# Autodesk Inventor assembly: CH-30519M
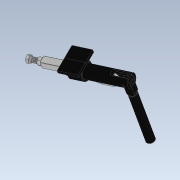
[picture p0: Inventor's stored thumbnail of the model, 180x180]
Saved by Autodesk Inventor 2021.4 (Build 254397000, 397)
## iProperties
Company: Microsoft
Created: 2017-11
Part Number: CH-30519M
Description: STEP AP203
Document SubType Name: Assembly
Designer: user
Stock Number: DOCISK LINIOWY
Sending System: SolidWorks 2015
Preprocessor: SwSTEP 2.0
Title: CH-30519M.STEP
Author: Windows
Revision Number: ÈÎºÎ
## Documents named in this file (14)
- Y:\CAD CLAMPS\Dociski liniowe\CH-30519M\CH-30519M.iam
- Y:\CAD CLAMPS\Dociski liniowe\CH-30519M\CH-30519M-05 CREST STALK.ipt
- Y:\CAD CLAMPS\Dociski liniowe\CH-30519M\CH-30519M-02 LEAD TUBE.ipt
- Y:\CAD CLAMPS\Dociski liniowe\CH-30519M\CH-30519M-04 CONNECTING-PLATE.ipt
- Y:\CAD CLAMPS\Dociski liniowe\CH-30519M\CH-30519M-10.ipt
- Y:\CAD CLAMPS\Dociski liniowe\CH-30519M\CH-30519M-07.ipt
- Y:\CAD CLAMPS\Dociski liniowe\CH-30519M\CH-30519M-06.ipt
- Y:\CAD CLAMPS\Dociski liniowe\CH-30519M\CH-30519M-08.ipt
- Y:\CAD CLAMPS\Dociski liniowe\CH-30519M\CH-30519M-03 HANDLE.ipt
- Y:\CAD CLAMPS\Dociski liniowe\CH-30519M\CH-30519M-11.ipt
- Y:\CAD CLAMPS\Dociski liniowe\CH-30519M\CH-30519M-09.ipt
- Y:\CAD CLAMPS\Dociski liniowe\CH-30519M\M12 Nut.ipt
- Y:\CAD CLAMPS\Dociski liniowe\CH-30519M\M12X50.ipt
- Y:\CAD CLAMPS\Dociski liniowe\CH-30519M\30519-01_Ä¬ÈÏ_°´¼Ó¹¤_.ipt
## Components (14 placed, 14 different names)
1. CH-30519M-05 CREST STALK_1
2. CH-30519M-02 LEAD TUBE_2
3. CH-30519M-04 CONNECTING-PLATE_3
4. CH-30519M-10_4
5. CH-30519M-10_5
6. CH-30519M-07_6
7. CH-30519M-06_7
8. CH-30519M-08_8
9. CH-30519M-03 HANDLE_9
10. CH-30519M-11_10
11. CH-30519M-09_11
12. M12 Nut_12
13. M12X50_13
14. 30519-01_Ä¬ÈÏ<°´¼Ó¹¤>_14
